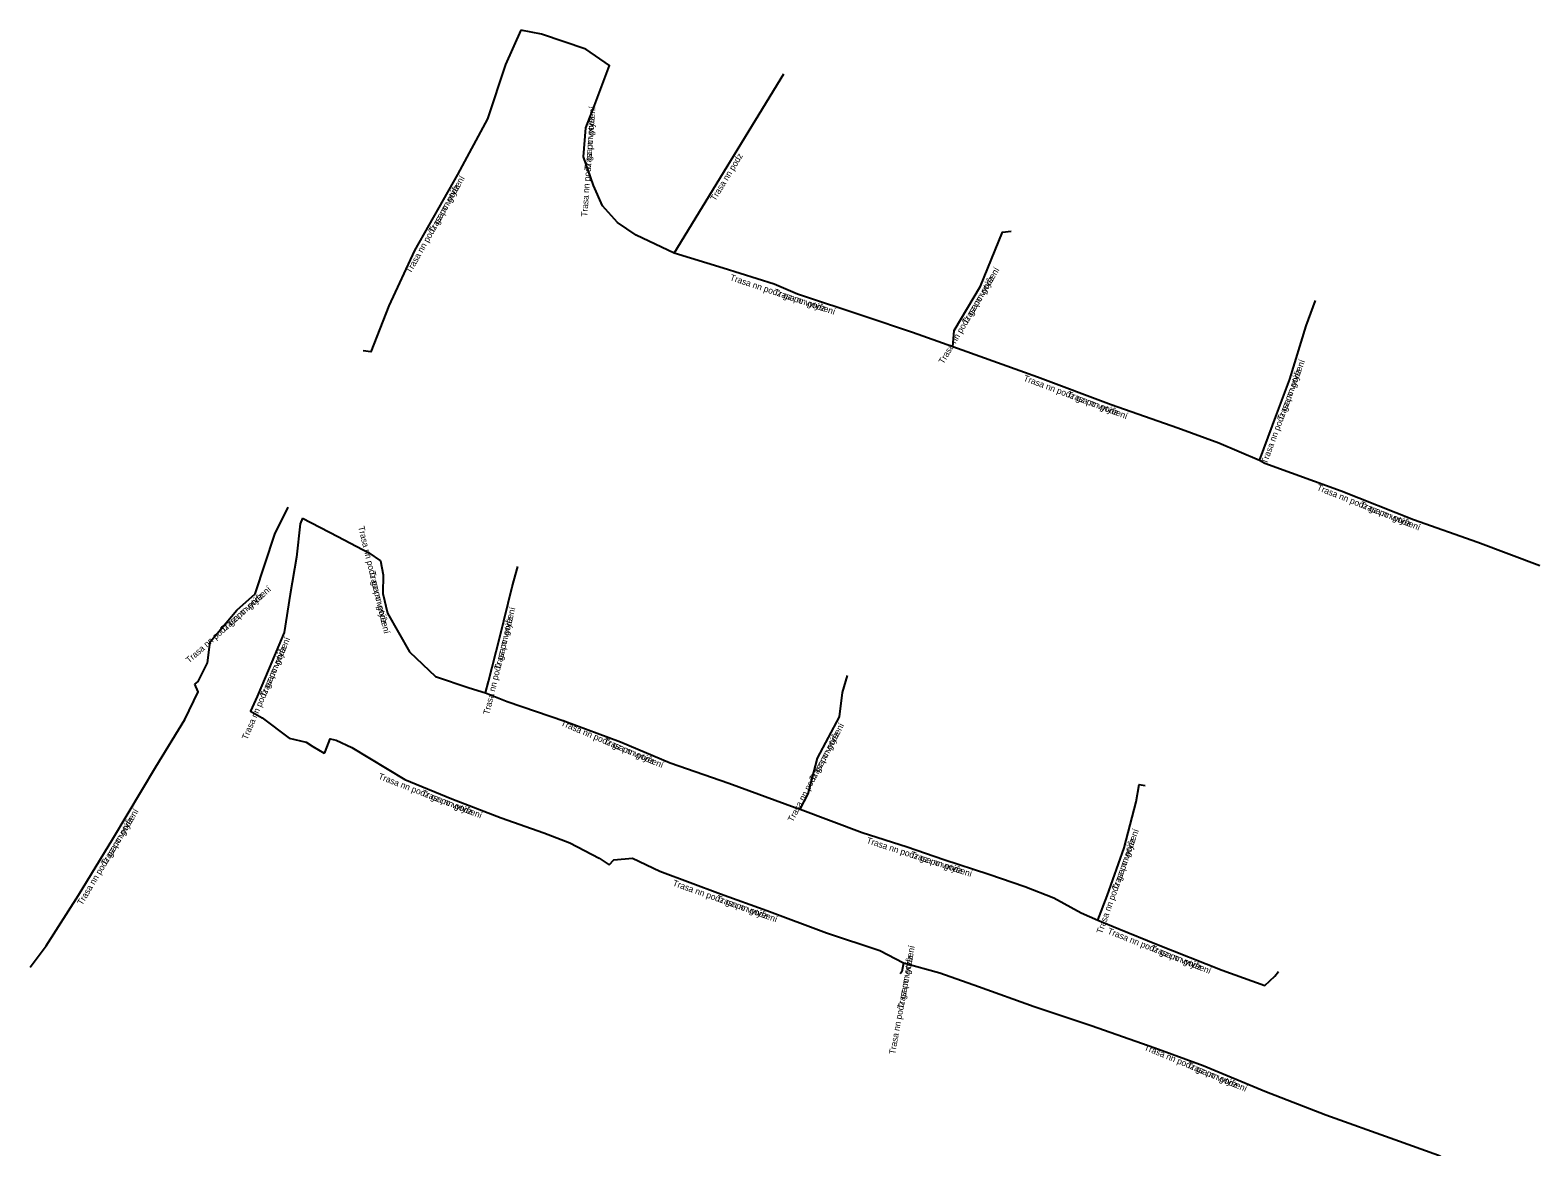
# Model space of a CAD drawing. Extents: x -703240 to -702678, y -1007635 to -1007322.
# Drawn here: x -703239.9 to -703120.1, y -1007473.5 to -1007384.7 of the extents above; entities that cross this region are included whole.
import ezdxf

# ---------------------------------------------------------------- set-up
doc = ezdxf.new("R2010")
doc.units = 0
doc.layers.add('Popiskový text - Ostatní atributy Trasy', color=7, linetype='Continuous')
doc.layers.add('Spojnice NN', color=7, linetype='Continuous')

msp = doc.modelspace()

# ---------------------------------------------------------------- linework, layer by layer
at = {"layer": 'Spojnice NN'}
for points in [[(-703200.89, -1007384.7), (-703202.1, -1007387.44), (-703203.55, -1007391.75), (-703205.92, -1007396.18), (-703209.33, -1007402.21), (-703211.38, -1007406.6), (-703212.82, -1007410.26), (-703213.43, -1007410.2)], [(-703200.89, -1007384.7), (-703202.1, -1007387.44), (-703203.55, -1007391.75), (-703205.92, -1007396.18), (-703209.33, -1007402.21), (-703211.38, -1007406.6), (-703212.82, -1007410.26), (-703213.43, -1007410.2)], [(-703188.72, -1007402.42), (-703191.72, -1007400.99), (-703193.22, -1007400), (-703194.41, -1007398.65), (-703195.13, -1007397.05), (-703195.91, -1007394.77), (-703195.74, -1007392.46), (-703195.04, -1007390.69), (-703193.85, -1007387.5), (-703195.74, -1007386.22), (-703199.26, -1007385.01), (-703200.89, -1007384.7)], [(-703188.72, -1007402.42), (-703191.72, -1007400.99), (-703193.22, -1007400), (-703194.41, -1007398.65), (-703195.13, -1007397.05), (-703195.91, -1007394.77), (-703195.74, -1007392.46), (-703195.04, -1007390.69), (-703193.85, -1007387.5), (-703195.74, -1007386.22), (-703199.26, -1007385.01), (-703200.89, -1007384.7)], [(-703188.72, -1007402.42), (-703180, -1007388.18)], [(-703166.58, -1007409.88), (-703166.46, -1007408.58), (-703164.37, -1007405.05), (-703162.63, -1007400.75), (-703161.92, -1007400.68)], [(-703166.58, -1007409.88), (-703166.46, -1007408.58), (-703164.37, -1007405.05), (-703162.63, -1007400.75), (-703161.92, -1007400.68)], [(-703166.58, -1007409.88), (-703169.77, -1007408.73), (-703173.57, -1007407.45), (-703178.92, -1007405.67), (-703180.76, -1007404.9), (-703184.82, -1007403.62), (-703188.72, -1007402.42)], [(-703166.58, -1007409.88), (-703169.77, -1007408.73), (-703173.57, -1007407.45), (-703178.92, -1007405.67), (-703180.76, -1007404.9), (-703184.82, -1007403.62), (-703188.72, -1007402.42)], [(-703142.2, -1007418.9), (-703140.82, -1007415.2), (-703139.8, -1007412.45), (-703138.5, -1007408.2), (-703137.76, -1007406.19)], [(-703142.2, -1007418.9), (-703140.82, -1007415.2), (-703139.8, -1007412.45), (-703138.5, -1007408.2), (-703137.76, -1007406.19)], [(-703142.2, -1007418.9), (-703145.44, -1007417.52), (-703148.68, -1007416.34), (-703153.99, -1007414.48), (-703159.84, -1007412.29), (-703165.82, -1007410.14), (-703166.58, -1007409.88)], [(-703142.2, -1007418.9), (-703145.44, -1007417.52), (-703148.68, -1007416.34), (-703153.99, -1007414.48), (-703159.84, -1007412.29), (-703165.82, -1007410.14), (-703166.58, -1007409.88)], [(-703119.93, -1007427.27), (-703124.86, -1007425.43), (-703129.96, -1007423.61), (-703135.71, -1007421.33), (-703141.79, -1007419.13), (-703142.2, -1007418.9)], [(-703119.93, -1007427.27), (-703124.86, -1007425.43), (-703129.96, -1007423.61), (-703135.71, -1007421.33), (-703141.79, -1007419.13), (-703142.2, -1007418.9)], [(-703226.79, -1007436.67), (-703226.52, -1007436.46), (-703225.8, -1007434.99), (-703225.59, -1007433.32), (-703223.45, -1007430.8), (-703221.99, -1007429.5), (-703220.45, -1007424.77), (-703219.38, -1007422.62)], [(-703226.79, -1007436.67), (-703226.52, -1007436.46), (-703225.8, -1007434.99), (-703225.59, -1007433.32), (-703223.45, -1007430.8), (-703221.99, -1007429.5), (-703220.45, -1007424.77), (-703219.38, -1007422.62)], [(-703218.25, -1007423.48), (-703218.42, -1007423.93), (-703218.71, -1007426.58), (-703219.21, -1007429.52), (-703219.69, -1007432.58), (-703220.89, -1007435.4), (-703221.85, -1007437.65), (-703222.37, -1007438.83), (-703221.44, -1007439.36), (-703219.29, -1007440.98), (-703217.96, -1007441.3), (-703217.43, -1007441.63), (-703216.51, -1007442.16)], [(-703218.25, -1007423.48), (-703218.42, -1007423.93), (-703218.71, -1007426.58), (-703219.21, -1007429.52), (-703219.69, -1007432.58), (-703220.89, -1007435.4), (-703221.85, -1007437.65), (-703222.37, -1007438.83), (-703221.44, -1007439.36), (-703219.29, -1007440.98), (-703217.96, -1007441.3), (-703217.43, -1007441.63), (-703216.51, -1007442.16)], [(-703218.25, -1007423.48), (-703215.42, -1007424.93), (-703212.96, -1007426.25), (-703212.03, -1007426.88), (-703211.84, -1007427.98), (-703211.87, -1007429.46), (-703211.49, -1007431.03), (-703209.74, -1007434.12), (-703207.66, -1007436.08), (-703205.01, -1007436.98), (-703203.71, -1007437.37)], [(-703218.25, -1007423.48), (-703215.42, -1007424.93), (-703212.96, -1007426.25), (-703212.03, -1007426.88), (-703211.84, -1007427.98), (-703211.87, -1007429.46), (-703211.49, -1007431.03), (-703209.74, -1007434.12), (-703207.66, -1007436.08), (-703205.01, -1007436.98), (-703203.71, -1007437.37)], [(-703203.71, -1007437.37), (-703203.46, -1007436.46), (-703202.56, -1007432.94), (-703201.57, -1007428.93), (-703201.13, -1007427.33)], [(-703203.71, -1007437.37), (-703203.46, -1007436.46), (-703202.56, -1007432.94), (-703201.57, -1007428.93), (-703201.13, -1007427.33)], [(-703178.7, -1007446.61), (-703178.07, -1007445.4), (-703177.31, -1007442.57), (-703175.57, -1007439.28), (-703175.34, -1007437.33), (-703174.93, -1007435.99)], [(-703178.7, -1007446.61), (-703178.07, -1007445.4), (-703177.31, -1007442.57), (-703175.57, -1007439.28), (-703175.34, -1007437.33), (-703174.93, -1007435.99)], [(-703239.88, -1007459.18), (-703238.6, -1007457.48), (-703236.04, -1007453.46), (-703233.32, -1007448.98), (-703229.89, -1007443.26), (-703227.58, -1007439.49), (-703226.54, -1007437.28), (-703226.79, -1007436.67)], [(-703239.88, -1007459.18), (-703238.6, -1007457.48), (-703236.04, -1007453.46), (-703233.32, -1007448.98), (-703229.89, -1007443.26), (-703227.58, -1007439.49), (-703226.54, -1007437.28), (-703226.79, -1007436.67)], [(-703203.71, -1007437.37), (-703201.98, -1007438.06), (-703197.4, -1007439.63), (-703192.97, -1007441.26), (-703189.02, -1007442.93), (-703184.37, -1007444.54), (-703179.1, -1007446.48), (-703178.7, -1007446.61)], [(-703203.71, -1007437.37), (-703201.98, -1007438.06), (-703197.4, -1007439.63), (-703192.97, -1007441.26), (-703189.02, -1007442.93), (-703184.37, -1007444.54), (-703179.1, -1007446.48), (-703178.7, -1007446.61)], [(-703216.51, -1007442.16), (-703216.44, -1007442.06), (-703216.05, -1007441.02), (-703215.56, -1007441.12), (-703214.31, -1007441.7), (-703210.11, -1007444.25), (-703206.37, -1007445.78), (-703202.45, -1007447.3), (-703199.06, -1007448.49), (-703196.99, -1007449.29), (-703194.67, -1007450.51), (-703193.88, -1007451.05)], [(-703216.51, -1007442.16), (-703216.44, -1007442.06), (-703216.05, -1007441.02), (-703215.56, -1007441.12), (-703214.31, -1007441.7), (-703210.11, -1007444.25), (-703206.37, -1007445.78), (-703202.45, -1007447.3), (-703199.06, -1007448.49), (-703196.99, -1007449.29), (-703194.67, -1007450.51), (-703193.88, -1007451.05)], [(-703155.05, -1007455.44), (-703154.31, -1007453.51), (-703152.96, -1007449.69), (-703152.01, -1007446.04), (-703151.76, -1007444.64), (-703151.29, -1007444.73)], [(-703155.05, -1007455.44), (-703154.31, -1007453.51), (-703152.96, -1007449.69), (-703152.01, -1007446.04), (-703151.76, -1007444.64), (-703151.29, -1007444.73)], [(-703178.7, -1007446.61), (-703173.76, -1007448.47), (-703170.19, -1007449.6), (-703167.29, -1007450.62), (-703163.72, -1007451.78), (-703160.84, -1007452.76), (-703158.55, -1007453.65), (-703156.36, -1007454.86), (-703155.05, -1007455.44)], [(-703178.7, -1007446.61), (-703173.76, -1007448.47), (-703170.19, -1007449.6), (-703167.29, -1007450.62), (-703163.72, -1007451.78), (-703160.84, -1007452.76), (-703158.55, -1007453.65), (-703156.36, -1007454.86), (-703155.05, -1007455.44)], [(-703193.88, -1007451.05), (-703193.51, -1007450.65), (-703192.02, -1007450.5), (-703189.85, -1007451.54), (-703185.04, -1007453.35), (-703181.35, -1007454.66), (-703176.6, -1007456.43), (-703172.37, -1007457.84), (-703170.48, -1007458.83)], [(-703193.88, -1007451.05), (-703193.51, -1007450.65), (-703192.02, -1007450.5), (-703189.85, -1007451.54), (-703185.04, -1007453.35), (-703181.35, -1007454.66), (-703176.6, -1007456.43), (-703172.37, -1007457.84), (-703170.48, -1007458.83)], [(-703155.05, -1007455.44), (-703153.39, -1007456.12), (-703150.39, -1007457.35), (-703145.17, -1007459.42), (-703141.77, -1007460.62), (-703140.98, -1007459.88), (-703140.7, -1007459.51)], [(-703155.05, -1007455.44), (-703153.39, -1007456.12), (-703150.39, -1007457.35), (-703145.17, -1007459.42), (-703141.77, -1007460.62), (-703140.98, -1007459.88), (-703140.7, -1007459.51)], [(-703170.48, -1007458.83), (-703170.61, -1007459.54), (-703170.75, -1007459.71)], [(-703170.48, -1007458.83), (-703170.61, -1007459.54), (-703170.75, -1007459.71)], [(-703170.48, -1007458.83), (-703167.59, -1007459.63), (-703164.52, -1007460.71), (-703160.1, -1007462.3), (-703155.58, -1007463.8), (-703150.53, -1007465.57), (-703146.69, -1007466.98), (-703141.78, -1007469.02), (-703136.93, -1007470.9), (-703131.46, -1007472.86), (-703127.97, -1007474.1), (-703123.99, -1007476.28), (-703121.27, -1007477.68), (-703120.71, -1007478.36), (-703120.24, -1007478.76)], [(-703170.48, -1007458.83), (-703167.59, -1007459.63), (-703164.52, -1007460.71), (-703160.1, -1007462.3), (-703155.58, -1007463.8), (-703150.53, -1007465.57), (-703146.69, -1007466.98), (-703141.78, -1007469.02), (-703136.93, -1007470.9), (-703131.46, -1007472.86), (-703127.97, -1007474.1), (-703123.99, -1007476.28), (-703121.27, -1007477.68), (-703120.71, -1007478.36), (-703120.24, -1007478.76)]]:
    msp.add_lwpolyline(points, dxfattribs=at)

# ---------------------------------------------------------------- texts
at = {"layer": 'Popiskový text - Ostatní atributy Trasy'}
for s, rotation, p in [('Trasa nn podz gz po vytýèení', 85.791, (-703195.61, -1007399.54)), ('Trasa nn podz', 85.791, (-703195.34, -1007395.86)), ('Trasa nn podz', 58.5361, (-703185.45, -1007398.32)), ('Trasa nn podz gz po vytýèení', 60.5116, (-703209.64, -1007404.08)), ('Trasa nn podz', 60.5116, (-703207.83, -1007400.87)), ('Trasa nn podz gz po vytýèení', 59.3716, (-703167.31, -1007411.28)), ('Trasa nn podz gz po vytýèení', 341.5972, (-703184.32, -1007404.56)), ('Trasa nn podz', 341.5972, (-703180.83, -1007405.72)), ('Trasa nn podz', 59.3716, (-703165.43, -1007408.11)), ('Trasa nn podz gz po vytýèení', 69.6497, (-703141.62, -1007419.22)), ('Trasa nn podz gz po vytýèení', 339.4762, (-703161, -1007412.55)), ('Trasa nn podz', 69.6497, (-703140.34, -1007415.77)), ('Trasa nn podz', 339.4762, (-703157.54, -1007413.84)), ('Trasa nn podz gz po vytýèení', 338.3706, (-703137.69, -1007421.24)), ('Trasa nn podz', 338.3706, (-703134.26, -1007422.6)), ('Trasa nn podz gz po vytýèení', 283.6061, (-703213.82, -1007424.18)), ('Trasa nn podz', 283.6061, (-703212.95, -1007427.76)), ('Trasa nn podz gz po vytýèení', 41.6822, (-703227.24, -1007435.04)), ('Trasa nn podz', 41.6822, (-703224.49, -1007432.59)), ('Trasa nn podz gz po vytýèení', 76.2161, (-703203.41, -1007439.14)), ('Trasa nn podz', 76.2161, (-703202.53, -1007435.56)), ('Trasa nn podz gz po vytýèení', 66.9487, (-703222.63, -1007441.14)), ('Trasa nn podz', 66.9487, (-703221.18, -1007437.75)), ('Trasa nn podz gz po vytýèení', 337.0821, (-703197.76, -1007439.94)), ('Trasa nn podz gz po vytýèení', 62.1267, (-703179.28, -1007447.68)), ('Trasa nn podz', 337.0821, (-703194.36, -1007441.38)), ('Trasa nn podz', 62.1267, (-703177.55, -1007444.42)), ('Trasa nn podz gz po vytýèení', 338.8059, (-703212.26, -1007444.19)), ('Trasa nn podz', 338.8059, (-703208.83, -1007445.52)), ('Trasa nn podz gz po vytýèení', 59.051, (-703235.75, -1007454.29)), ('Trasa nn podz', 59.051, (-703233.85, -1007451.13)), ('Trasa nn podz gz po vytýèení', 70.5364, (-703154.7, -1007456.56)), ('Trasa nn podz gz po vytýèení', 341.9995, (-703173.47, -1007449.3)), ('Trasa nn podz', 70.5364, (-703153.47, -1007453.09)), ('Trasa nn podz', 341.9995, (-703169.97, -1007450.43)), ('Trasa nn podz gz po vytýèení', 340.4544, (-703188.87, -1007452.68)), ('Trasa nn podz', 340.4544, (-703185.4, -1007453.91)), ('Trasa nn podz gz po vytýèení', 338.3691, (-703154.32, -1007456.49)), ('Trasa nn podz gz po vytýèení', 79.6242, (-703171.16, -1007466.13)), ('Trasa nn podz', 338.3691, (-703150.89, -1007457.85)), ('Trasa nn podz', 79.6242, (-703170.49, -1007462.51)), ('Trasa nn podz gz po vytýèení', 337.4382, (-703151.41, -1007465.72)), ('Trasa nn podz', 337.4382, (-703148.01, -1007467.14))]:
    msp.add_text(s, height=0.5, rotation=rotation, dxfattribs=at).set_placement(p)

doc.saveas('drawing.dxf')
